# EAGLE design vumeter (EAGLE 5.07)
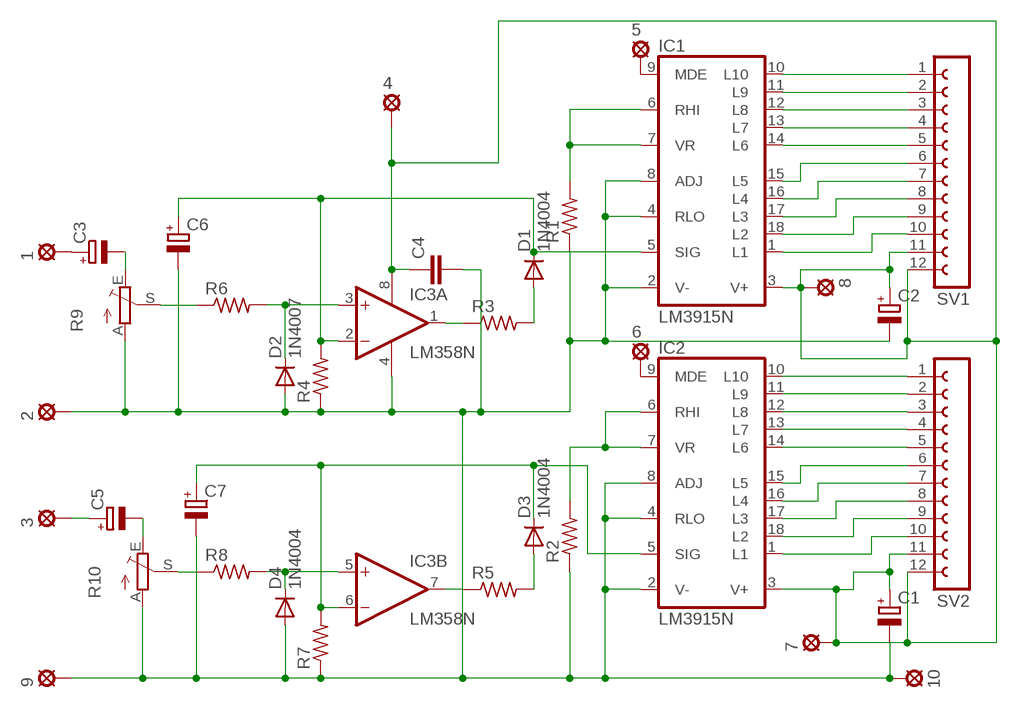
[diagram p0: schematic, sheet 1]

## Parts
1  SE11  [SE11]
2  SE11  [SE11]
3  SE11  [SE11]
4  SE11  [SE11]
5  SE11  [SE11]
6  SE11  [SE11]
7  SE11  [SE11]
8  SE11  [SE11]
9  SE11  [SE11]
10  SE11  [SE11]
C1  CPOL-EUE2.5-5  [E2,5-5]
C2  CPOL-EUE2.5-5  [E2,5-5]
C3  CPOL-EUE2.5-5  [E2,5-5]
C4  C-EU050-025X075  [C050-025X075]
C5  CPOL-EUE2.5-5  [E2,5-5]
C6  CPOL-EUE2.5-5  [E2,5-5]
C7  CPOL-EUE2.5-5  [E2,5-5]
D1  1N4004  [DO41-10]
D2  1N4007  1N4004  [DO41-10]
D3  1N4004  [DO41-10]
D4  1N4004  [DO41-10]
IC1  LM3915N  LM3914N  [DIL18]
IC2  LM3915N  LM3914N  [DIL18]
IC3  LM358N  [DIL08]
R1  R-US_0207/10  [0207/10]
R2  R-US_0207/10  [0207/10]
R3  R-US_0207/10  [0207/10]
R4  R-US_0207/10  [0207/10]
R5  R-US_0207/10  [0207/10]
R6  R-US_0207/10  [0207/10]
R7  R-US_0207/10  [0207/10]
R8  R-US_0207/10  [0207/10]
R9  TRIM_EU-LI10  [LI10]
R10  TRIM_EU-LI10  [LI10]
SV1  FE12-1  [FE12]
SV2  FE12-1  [FE12]

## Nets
N$1: 5.MP IC1.9(MDE)
N$2: IC1.6(RHI) IC1.7(VR) R1.2
N$3: 1.MP C3.+
N$4: IC1.10(L10) SV1.1
N$5: IC1.11(L9) SV1.2
N$6: IC1.12(L8) SV1.3
N$7: IC1.13(L7) SV1.4
N$8: IC1.14(L6) SV1.5
N$9: IC1.15(L5) SV1.6
N$10: IC1.16(L4) SV1.7
N$11: IC1.17(L3) SV1.8
N$12: IC1.18(L2) SV1.9
N$13: IC2.10(L10) SV2.1
N$14: IC1.1(L1) SV1.10
N$15: IC2.11(L9) SV2.2
N$16: IC2.12(L8) SV2.3
N$17: IC2.13(L7) SV2.4
N$18: IC2.14(L6) SV2.5
N$19: IC2.15(L5) SV2.6
N$20: IC2.16(L4) SV2.7
N$21: IC2.17(L3) SV2.8
N$22: IC2.18(L2) SV2.9
N$23: IC2.1(L1) SV2.10
N$24: IC2.6(RHI) IC2.7(VR) R2.2
N$26: 2.MP 9.MP 10.MP C1.- C2.- C4.2 C6.- C7.- D4.A IC1.2(V-) IC1.4(RLO) IC1.8(ADJ) IC2.2(V-) IC2.4(RLO) IC2.8(ADJ) R1.1 R2.1 R4.1 R7.1 R9.A R10.A
N$28: 4.MP 7.MP 8.MP C1.+ C2.+ C4.1 IC1.3(V+) IC2.3(V+) IC3.8(P:V+) SV1.11 SV1.12 SV2.11 SV2.12
N$29: 6.MP IC2.9(MDE)
N$30: IC3.1(A:OUT) R3.1
N$31: D1.A R3.2
N$32: 3.MP C5.+
N$33: R6.1 R9.S
N$34: C6.+ D1.C IC1.5(SIG) IC3.2(A:-IN) R4.2
N$35: C3.- R9.E
N$36: D2.C IC3.3(A:+IN) R6.2
N$38: IC3.7(B:OUT) R5.1
N$39: D3.A R5.2
N$40: C7.+ D3.C IC2.5(SIG) IC3.6(B:-IN) R7.2
N$41: D2.A
N$42: D4.C IC3.5(B:+IN) R8.2
N$43: R8.1 R10.S
N$44: C5.- R10.E
N$45: IC3.4(P:V-)

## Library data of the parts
1-10 = solpad:SE11: SOLDER PAD
C1-C3 C5-C7 = resistor:CPOL-EU: POLARIZED CAPACITOR, European symbol
C4 = resistor:C-EU: CAPACITOR, European symbol
D1-D4 = diode:1N4004: DIODE
IC1 IC2 = linear:LM3914N: LED DRIVER senses analog voltage levels and drives 10 LEDs
IC3 = linear:LM358: OP AMP also LM158; LM258; LM2904 Source: http://cache.national.com/ds/LM/LM158.pdf
R1-R8 = resistor:R-US_: RESISTOR, American symbol
R9 R10 = pot:TRIM_EU-: POTENTIOMETER
SV1 SV2 = con-lsta:FE12-1: FEMALE HEADER

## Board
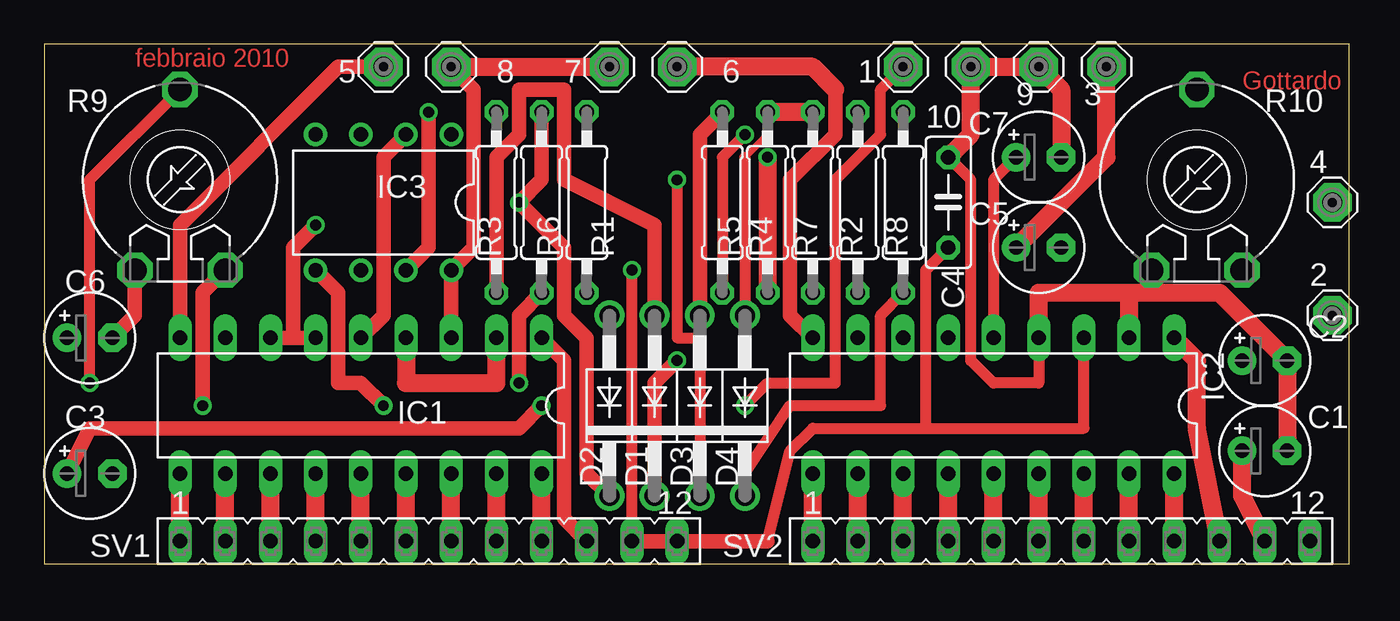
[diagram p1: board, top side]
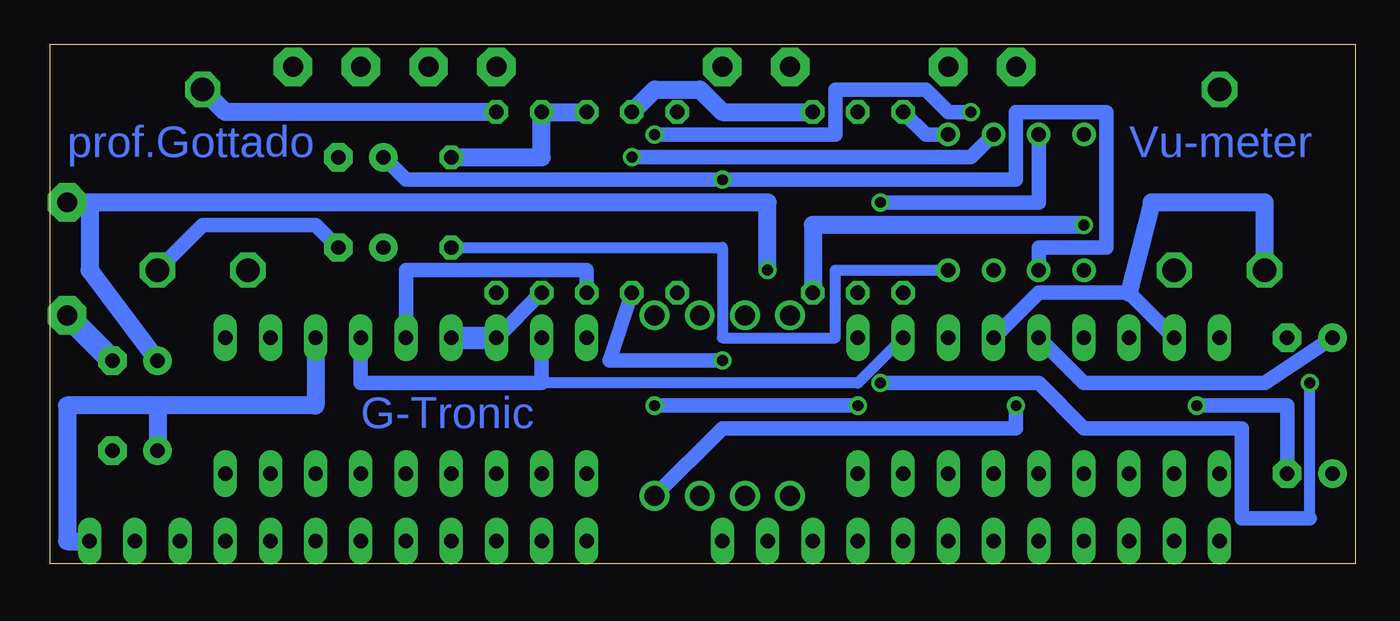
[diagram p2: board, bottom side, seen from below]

Size 73.33 x 29.2 mm. Coordinates in mm from the lower left corner, seen from the top.
Outline: 0,0 73.33,0 73.33,29.2 0,29.2 0,0
Copper layers (1*16): Top 0.035mm / dielectric 1.5mm / Bottom 0.035mm
Design rules "default": minimum track width 10mil, minimum drill 24mil, track to track 8mil, track to pad 8mil, pad to pad 8mil, via to via 8mil, smd to smd 8mil, copper to edge 40mil, drill to drill 8mil, minimum pad ring 10mil, minimum via ring 8mil, stop-mask expansion 4mil, vias tented up to drill 0mil, thermal gap 10mil

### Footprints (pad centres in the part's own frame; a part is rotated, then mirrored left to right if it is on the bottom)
SE11 = drill 1.118 pad 2.159 octagon: MP 0,0
E2,5-5 = drill 0.813 pad 1.6 round: + -1.27,0 | drill 0.813 pad 1.6 octagon: - 1.27,0
C050-025X075 = drill 0.813 octagon: 1 -2.54,0; 2 2.54,0
DO41-10 = drill 1.118 round: A 5.08,0; C -5.08,0
DIL18 = drill 0.813 long: 1 -10.16,-3.81; 2 -7.62,-3.81; 3 -5.08,-3.81; 4 -2.54,-3.81; 5 0,-3.81; 6 2.54,-3.81; 7 5.08,-3.81; 8 7.62,-3.81; 9 10.16,-3.81; 10 10.16,3.81; 11 7.62,3.81; 12 5.08,3.81; 13 2.54,3.81; 14 0,3.81; 15 -2.54,3.81; 16 -5.08,3.81; 17 -7.62,3.81; 18 -10.16,3.81
DIL08 = drill 0.813 pad 1.27 round: 1 -3.81,-3.81; 2 -1.27,-3.81; 3 1.27,-3.81; 4 3.81,-3.81; 5 3.81,3.81; 6 1.27,3.81; 7 -1.27,3.81; 8 -3.81,3.81
0207/10 = drill 0.813 octagon: 1 -5.08,0; 2 5.08,0
LI10 = drill 1.321 octagon: A -2.54,-5.08; E 2.54,-5.08; S 0,5.08
FE12 = drill 0.813 long: 1 -13.97,0; 2 -11.43,0; 3 -8.89,0; 4 -6.35,0; 5 -3.81,0; 6 -1.27,0; 7 1.27,0; 8 3.81,0; 9 6.35,0; 10 8.89,0; 11 11.43,0; 12 13.97,0

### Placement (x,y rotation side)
1  48.26,27.94 0 top
2  72.39,13.97 0 top
3  59.69,27.94 0 top
4  72.39,20.32 0 top
5  19.05,27.94 0 top
6  35.56,27.94 0 top
7  31.75,27.94 0 top
8  22.86,27.94 0 top
9  55.88,27.94 0 top
10  52.07,27.94 0 top
C1  68.58,6.35 0 top
C2  68.58,11.43 0 top
C3  2.54,5.08 0 top
C4  50.8,20.32 90 top
C5  55.88,17.78 0 top
C6  2.54,12.7 0 top
C7  55.88,22.86 0 top
D1  34.29,8.89 90 top
D2  31.75,8.89 90 top
D3  36.83,8.89 90 top
D4  39.37,8.89 90 top
IC1  17.78,8.89 180 top
IC2  53.34,8.89 180 top
IC3  19.05,20.32 180 top
R1  30.48,20.32 270 top
R2  45.72,20.32 270 top
R3  25.4,20.32 270 top
R4  40.64,20.32 270 top
R5  38.1,20.32 90 top
R6  27.94,20.32 90 top
R7  43.18,20.32 270 top
R8  48.26,20.32 270 top
R9  7.62,21.59 0 top
R10  64.77,21.59 0 top
SV1  21.59,1.27 0 top
SV2  57.15,1.27 0 top

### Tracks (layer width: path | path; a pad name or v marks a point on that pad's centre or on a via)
N$1
  Top 0.813: IC1.9 7.62,19.05 16.51,27.94 5.MP
N$2  (via drill 0.61)
  Top 0.813: 13.97,12.7 IC1.6 | IC1.7 13.97,12.7 | v15.24,19.05 13.97,17.78 13.97,12.7
  Bottom 1.016: R1.2 30.48,19.05 v15.24,19.05
N$3  (via drill 0.61)
  Top 0.61: v39.37,8.89 40.64,10.16 44.45,10.16 44.45,21.59 46.99,24.13 46.99,26.67 1.MP
  Top 0.813: C3.+ 2.54,7.62 26.67,7.62 v27.94,8.89
  Bottom 0.813: v27.94,8.89 v39.37,8.89
N$4
  Top 1.016: SV1.1 IC1.10
N$5
  Top 1.016: SV1.2 IC1.11
N$6
  Top 1.016: SV1.3 IC1.12
N$7
  Top 1.016: SV1.4 IC1.13
N$8
  Top 1.016: SV1.5 IC1.14
N$9
  Top 1.016: SV1.6 IC1.15
N$10
  Top 1.016: SV1.7 IC1.16
N$11
  Top 1.016: SV1.8 IC1.17
N$12
  Top 1.016: SV1.9 IC1.18
N$13
  Top 1.016: SV2.1 IC2.10
N$14
  Top 0.813: SV1.10 29.21,2.54 29.21,11.43 IC1.1
N$15
  Top 1.016: SV2.2 IC2.11
N$16
  Top 1.016: SV2.3 IC2.12
N$17
  Top 1.016: SV2.4 IC2.13
N$18
  Top 1.016: SV2.5 IC2.14
N$19
  Top 1.016: SV2.6 IC2.15
N$20
  Top 1.016: SV2.7 IC2.16
N$21
  Top 1.016: SV2.8 IC2.17
N$22
  Top 1.016: SV2.9 IC2.18
N$23
  Top 1.016: SV2.10 64.77,7.62 64.77,11.43 IC2.1
N$24
  Bottom 0.813: R2.2 IC2.7
  Bottom 1.27: IC2.7 IC2.6
N$26
  Top 0.406: 40.64,24.13 39.37,22.86
  Top 0.61: 39.37,22.86 D4.A | R4.1 40.64,24.13 | C4.2 52.07,21.59 52.07,11.43 53.34,10.16 55.88,10.16 IC2.4
  Top 0.813: C6.- 5.08,13.97 R9.A
  Top 1.016: C4.2 52.07,24.13 10.MP 9.MP 57.15,26.67 C7.- | R7.1 R4.1 | C1.- C2.- 66.04,15.24 62.23,15.24 | 60.96,15.24 IC2.2 | IC1.4 20.32,10.16 25.4,10.16 IC1.2 | 60.96,15.24 55.88,15.24 IC2.4 | 60.96,15.24 62.23,15.24 | 62.23,15.24 R10.A
  Bottom 0.61: IC1.2 27.94,10.16 45.72,10.16
  Bottom 0.813: IC2.8 45.72,10.16 55.88,10.16 IC2.4 | IC1.8 12.7,15.24 17.78,15.24 IC1.4
  Bottom 1.016: R1.1 35.56,25.4 36.83,26.67 39.37,26.67 R4.1 | R7.1 R2.1 45.72,22.86 C4.2 | R9.A 5.08,20.32 11.43,20.32 12.7,15.24
  Bottom 1.27: C2.- 2.MP
N$28  (via drill 0.61)
  Top 0.61: 40.64,1.27 41.91,6.35 43.18,7.62 49.53,7.62 | 49.53,7.62 58.42,7.62 IC2.3 | C4.1 49.53,16.51 49.53,7.62 | SV1.11 v33.02,16.51
  Top 0.813: IC1.3 IC3.8 24.13,17.78 24.13,26.67 8.MP | SV1.11 SV1.12 | SV1.12 34.29,1.27 | SV1.12 40.64,1.27
  Top 1.016: 8.MP 7.MP | SV2.11 67.31,3.81 C1.+
  Bottom 0.61: IC3.8 29.21,16.51 29.21,12.7 35.56,12.7 35.56,17.78 C4.1
  Bottom 1.016: SV2.12 72.39,1.27 72.39,8.89 67.31,8.89 | 67.31,8.89 58.42,8.89 IC2.3 | v33.02,16.51 33.02,20.32 71.12,20.32 | 71.12,20.32 71.12,16.51 C2.+ | 67.31,8.89 C1.+ | 71.12,20.32 4.MP
N$29
  Top 0.813: IC2.9 41.91,13.97 41.91,21.59 44.45,24.13 44.45,26.67
  Top 1.016: 44.45,26.67 43.18,27.94 6.MP
N$30
  Bottom 0.813: IC3.1 24.13,24.13 R3.1
N$31
  Top 0.813: R3.2 25.4,22.86 26.67,24.13 26.67,26.67 29.21,26.67 29.21,21.59 34.29,19.05 D1.A
N$32
  Top 1.016: C5.+ 59.69,22.86 3.MP
N$33  (via drill 0.61)
  Top 0.61: v2.54,10.16 2.54,21.59 R9.S
  Top 0.813: R6.1 26.67,13.97 v26.67,10.16
  Bottom 0.61: 2.54,2.54 v2.54,10.16
  Bottom 0.813: v26.67,10.16 17.78,10.16 15.24,7.62 6.35,7.62 6.35,2.54 2.54,2.54
N$34  (via drill 0.61)
  Top 0.813: v35.56,11.43 34.29,10.16 D1.C | IC1.5 19.05,13.97 19.05,22.86 IC3.2
  Top 1.016: v40.64,22.86 R4.2
  Bottom 0.813: R4.2 41.91,11.43 40.64,11.43 v35.56,11.43 | C6.+ 5.08,10.16 15.24,10.16 IC1.5 | v40.64,22.86 21.59,22.86 IC3.2
N$35  (via drill 0.61)
  Top 0.813: v8.89,8.89 8.89,15.24 R9.E
  Bottom 0.813: C3.- 3.81,8.89 v8.89,8.89
N$36  (via drill 0.61)
  Top 0.813: R6.2 27.94,21.59 v26.67,20.32 29.21,17.78 29.21,13.97 30.48,12.7 30.48,5.08 D2.C
  Bottom 0.813: IC3.3 17.78,20.32 v26.67,20.32
N$38  (via drill 0.61)
  Top 0.61: v39.37,24.13 38.1,22.86 R5.1
  Top 0.813: IC3.7 21.59,17.78 v21.59,25.4
  Bottom 0.813: v21.59,25.4 22.86,25.4 24.13,26.67 29.21,26.67 29.21,24.13 v39.37,24.13
N$39
  Top 0.813: R5.2 36.83,24.13 D3.A
N$40  (via drill 0.61)
  Top 0.61: IC2.5 53.34,21.59 C7.+ | D3.C 36.83,12.7 35.56,12.7 v35.56,21.59
  Bottom 0.813: IC3.6 17.78,17.78 13.97,17.78 13.97,25.4 19.05,25.4 19.05,21.59 v35.56,21.59 53.34,21.59 C7.+ | R7.2 43.18,16.51 53.34,16.51 IC2.5
N$42  (via drill 0.61)
  Top 0.61: R8.2 46.99,13.97 46.99,8.89 41.91,8.89 39.37,5.08 D4.C
  Top 0.813: IC3.5 16.51,15.24 16.51,10.16 17.78,10.16 v19.05,8.89
  Bottom 0.813: v19.05,8.89 19.05,7.62 35.56,7.62 D4.C
N$43
  Bottom 1.016: R8.1 63.5,25.4 R10.S
N$44
  Bottom 0.813: C5.- 58.42,19.05 64.77,19.05 R10.E

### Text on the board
Top: febbraio 2010 | Gottardo
Bottom: Vu-meter | prof.Gottado | G-Tronic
